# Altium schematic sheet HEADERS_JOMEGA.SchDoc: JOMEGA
size A3; Author: Silvio Navaretti; CompanyName: ARDUINO; DrawnBy: Silvio Navaretti; Engineer: Silvio Navaretti; Organization: ARDUINO; SheetNumber: 22; SheetTotal: 51; RevAuthor: Silvio Navaretti
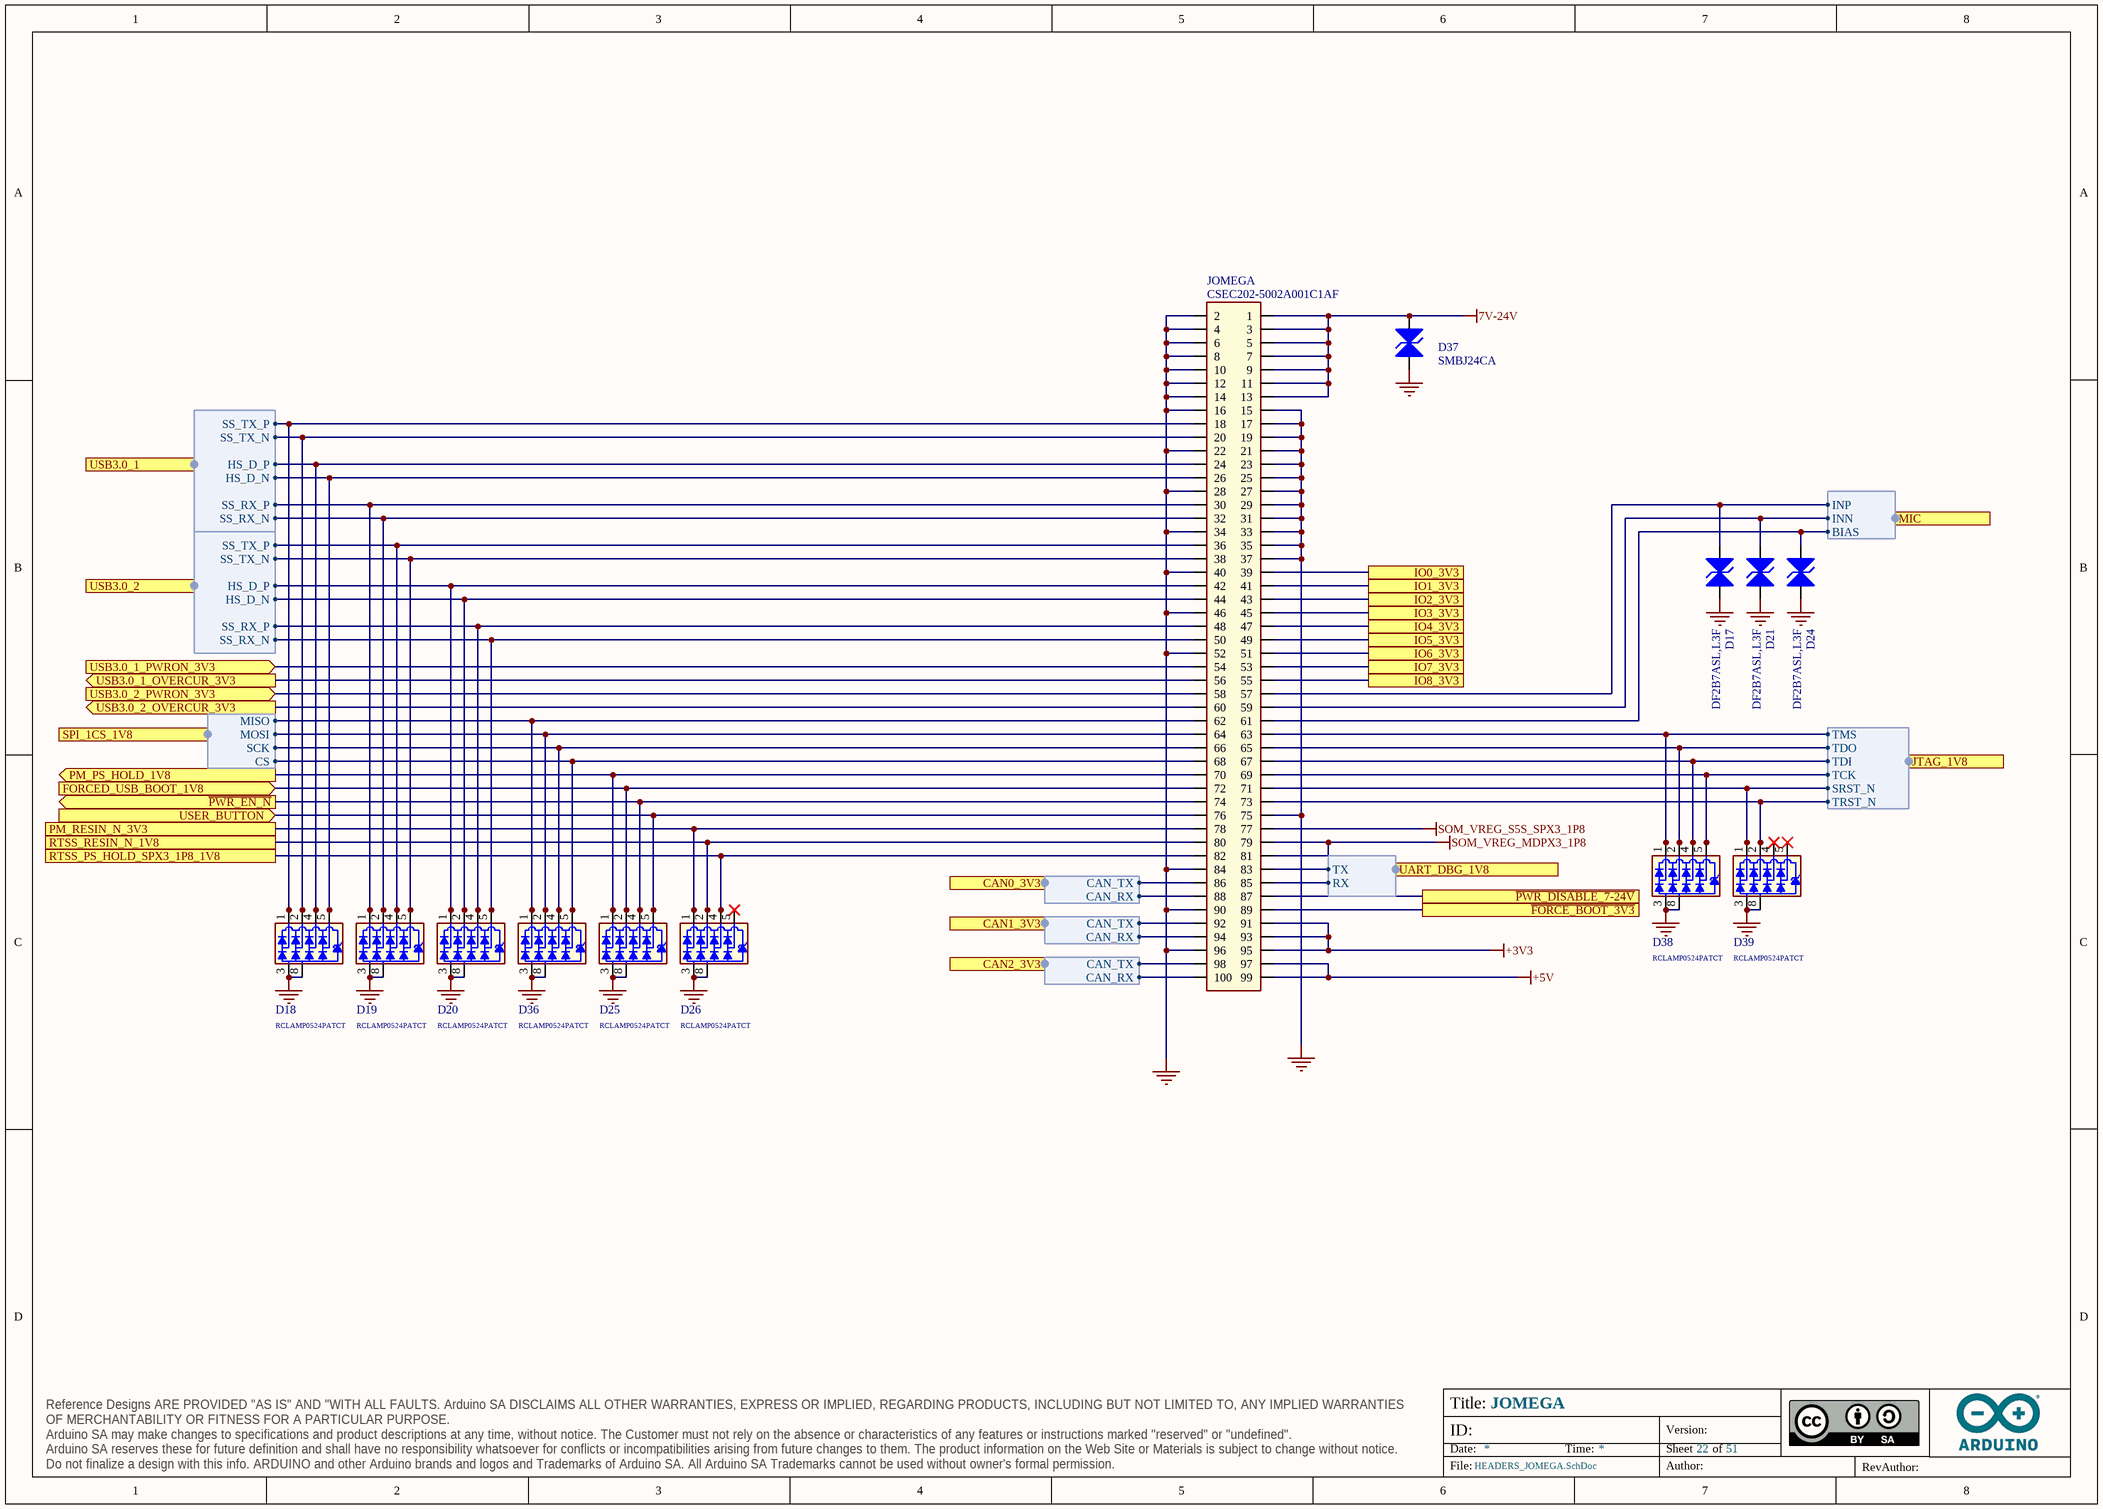
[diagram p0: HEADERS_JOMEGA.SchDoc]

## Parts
D17  DF2B7ASL,L3F  [DF2B7ASL,L3F]
D18  RCLAMP0524PATCT  [SLP2510P8]
D19  RCLAMP0524PATCT  [SLP2510P8]
D20  RCLAMP0524PATCT  [SLP2510P8]
D21  DF2B7ASL,L3F  [DF2B7ASL,L3F]
D24  DF2B7ASL,L3F  [DF2B7ASL,L3F]
D25  RCLAMP0524PATCT  [SLP2510P8]
D26  RCLAMP0524PATCT  [SLP2510P8]
D36  RCLAMP0524PATCT  [SLP2510P8]
D37  SMBJ24CA  [SMB_NOPOLARITY]
D38  RCLAMP0524PATCT  [SLP2510P8]
D39  RCLAMP0524PATCT  [SLP2510P8]
JOMEGA  CSEC202-5002A001C1AF  [CSEC202-5002A001C1AF]

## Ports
CAN0_3V3 (out, harness CAN), CAN1_3V3 (out, harness CAN), CAN2_3V3 (out, harness CAN), FORCED_USB_BOOT_1V8 (in), IO0_3V3, IO1_3V3, IO2_3V3, IO3_3V3, IO4_3V3, IO5_3V3, IO6_3V3, IO7_3V3, IO8_3V3, JTAG_1V8 (out, harness SOM_SAIL_JTAG), MIC (out, harness MIC), PM_PS_HOLD_1V8 (out), PM_RESIN_N_3V3, RTSS_PS_HOLD_SPX3_1P8_1V8, RTSS_RESIN_N_1V8, SPI_1CS_1V8 (in, harness SPI), UART_DBG_1V8 (harness UART), USB3.0_1 (out, harness SOM_MD_USB0), USB3.0_1_OVERCUR_3V3 (out), USB3.0_1_PWRON_3V3 (in), USB3.0_2 (out, harness SOM_MD_USB0), USB3.0_2_OVERCUR_3V3 (out), USB3.0_2_PWRON_3V3 (in), USER_BUTTON (in), ~{FORCE_BOOT_3V3}, ~{PWR_DISABLE_7-24V}, ~{PWR_EN_N} (out)

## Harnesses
MIC: INP, INN, BIAS
SOM_SAIL_JTAG: TMS, TDO, TDI, TCK, SRST_N, TRST_N
SOM_MD_USB0: SS_TX_N, SS_TX_P, HS_D_P, HS_D_N, SS_RX_P, SS_RX_N
SPI: SCK, MISO, MOSI, CS
CAN: CAN_TX, CAN_RX
UART: TX, RX

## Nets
7V-24V: D37.2(A2) JOMEGA.1 JOMEGA.3 JOMEGA.5 JOMEGA.7 JOMEGA.9 JOMEGA.11 JOMEGA.13
+3V3: JOMEGA.91 JOMEGA.93 JOMEGA.95
+5V: JOMEGA.97 JOMEGA.99
GND: D17.1(A1) D18.3 D18.8 D19.3 D19.8 D20.3 D20.8 D21.1(A1) D24.1(A1) D25.3 D25.8 D26.3 D26.8 D36.3 D36.8 D37.1(A1) D38.3 D38.8 D39.3 D39.8 JOMEGA.2 JOMEGA.4 JOMEGA.6 JOMEGA.8 JOMEGA.10 JOMEGA.12 JOMEGA.14 JOMEGA.15 JOMEGA.16 JOMEGA.17 JOMEGA.19 JOMEGA.21 JOMEGA.22 JOMEGA.23 JOMEGA.25 JOMEGA.27 JOMEGA.28 JOMEGA.29 JOMEGA.31 JOMEGA.33 JOMEGA.34 JOMEGA.35 JOMEGA.37 JOMEGA.40 JOMEGA.46 JOMEGA.52 JOMEGA.75 JOMEGA.84 JOMEGA.90 JOMEGA.96
SOM_VREG_MDPX3_1P8: JOMEGA.79 JOMEGA.81
SOM_VREG_S5S_SPX3_1P8: JOMEGA.77
~{FORCE_BOOT_3V3}: JOMEGA.89 ; port ~{FORCE_BOOT_3V3}
FORCED_USB_BOOT_1V8: D25.2 D25.9 JOMEGA.72 ; port FORCED_USB_BOOT_1V8
IO0_3V3: JOMEGA.39 ; port IO0_3V3
IO1_3V3: JOMEGA.41 ; port IO1_3V3
IO2_3V3: JOMEGA.43 ; port IO2_3V3
IO3_3V3: JOMEGA.45 ; port IO3_3V3
IO4_3V3: JOMEGA.47 ; port IO4_3V3
IO5_3V3: JOMEGA.49 ; port IO5_3V3
IO6_3V3: JOMEGA.51 ; port IO6_3V3
IO7_3V3: JOMEGA.53 ; port IO7_3V3
IO8_3V3: JOMEGA.55 ; port IO8_3V3
~{PWR_DISABLE_7-24V}: JOMEGA.87 ; port ~{PWR_DISABLE_7-24V}
~{PWR_EN_N}: D25.4 D25.7 JOMEGA.74 ; port ~{PWR_EN_N}
PM_PS_HOLD_1V8: D25.1 D25.10 JOMEGA.70 ; port PM_PS_HOLD_1V8
PM_RESIN_N_3V3: D26.1 D26.10 JOMEGA.78 ; port PM_RESIN_N_3V3
RTSS_PS_HOLD_SPX3_1P8_1V8: D26.4 D26.7 JOMEGA.82 ; port RTSS_PS_HOLD_SPX3_1P8_1V8
RTSS_RESIN_N_1V8: D26.2 D26.9 JOMEGA.80 ; port RTSS_RESIN_N_1V8
USB3.0_1_OVERCUR_3V3: JOMEGA.56 ; port USB3.0_1_OVERCUR_3V3
USB3.0_1_PWRON_3V3: JOMEGA.54 ; port USB3.0_1_PWRON_3V3
USB3.0_2_OVERCUR_3V3: JOMEGA.60 ; port USB3.0_2_OVERCUR_3V3
USB3.0_2_PWRON_3V3: JOMEGA.58 ; port USB3.0_2_PWRON_3V3
USER_BUTTON: D25.5 D25.6 JOMEGA.76 ; port USER_BUTTON
NetD17_2: D17.2(A2) JOMEGA.57 ; port MIC.INP
NetD18_1: D18.1 D18.10 JOMEGA.18 ; port USB3.0_1.SS_TX_P
NetD18_2: D18.2 D18.9 JOMEGA.20 ; port USB3.0_1.SS_TX_N
NetD18_4: D18.4 D18.7 JOMEGA.24 ; port USB3.0_1.HS_D_P
NetD18_5: D18.5 D18.6 JOMEGA.26 ; port USB3.0_1.HS_D_N
NetD19_1: D19.1 D19.10 JOMEGA.30 ; port USB3.0_1.SS_RX_P
NetD19_2: D19.2 D19.9 JOMEGA.32 ; port USB3.0_1.SS_RX_N
NetD19_4: D19.4 D19.7 JOMEGA.36 ; port USB3.0_2.SS_TX_P
NetD19_5: D19.5 D19.6 JOMEGA.38 ; port USB3.0_2.SS_TX_N
NetD20_1: D20.1 D20.10 JOMEGA.42 ; port USB3.0_2.HS_D_P
NetD20_2: D20.2 D20.9 JOMEGA.44 ; port USB3.0_2.HS_D_N
NetD20_4: D20.4 D20.7 JOMEGA.48 ; port USB3.0_2.SS_RX_P
NetD20_5: D20.5 D20.6 JOMEGA.50 ; port USB3.0_2.SS_RX_N
NetD21_2: D21.2(A2) JOMEGA.59 ; port MIC.INN
NetD24_2: D24.2(A2) JOMEGA.61 ; port MIC.BIAS
NetD26_5: D26.5 D26.6
NetD36_1: D36.1 D36.10 JOMEGA.62 ; port SPI_1CS_1V8.MISO
NetD36_2: D36.2 D36.9 JOMEGA.64 ; port SPI_1CS_1V8.MOSI
NetD36_4: D36.4 D36.7 JOMEGA.66 ; port SPI_1CS_1V8.SCK
NetD36_5: D36.5 D36.6 JOMEGA.68 ; port SPI_1CS_1V8.CS
NetD38_1: D38.1 D38.10 JOMEGA.63 ; port JTAG_1V8.TMS
NetD38_2: D38.2 D38.9 JOMEGA.65 ; port JTAG_1V8.TDO
NetD38_4: D38.4 D38.7 JOMEGA.67 ; port JTAG_1V8.TDI
NetD38_5: D38.5 D38.6 JOMEGA.69 ; port JTAG_1V8.TCK
NetD39_1: D39.1 D39.10 JOMEGA.71 ; port JTAG_1V8.SRST_N
NetD39_2: D39.2 D39.9 JOMEGA.73 ; port JTAG_1V8.TRST_N
NetD39_4: D39.4 D39.7
NetD39_5: D39.5 D39.6
NetJOMEGA_83: JOMEGA.83 ; port UART_DBG_1V8.TX
NetJOMEGA_85: JOMEGA.85 ; port UART_DBG_1V8.RX
NetJOMEGA_86: JOMEGA.86 ; port CAN0_3V3.CAN_TX
NetJOMEGA_88: JOMEGA.88 ; port CAN0_3V3.CAN_RX
NetJOMEGA_92: JOMEGA.92 ; port CAN1_3V3.CAN_TX
NetJOMEGA_94: JOMEGA.94 ; port CAN1_3V3.CAN_RX
NetJOMEGA_98: JOMEGA.98 ; port CAN2_3V3.CAN_TX
NetJOMEGA_100: JOMEGA.100 ; port CAN2_3V3.CAN_RX

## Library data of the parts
D17 D21 D24 = D0099-5: TVS BIDIRECTIONAL SMD Vr 5.5V, Vbr min 5.8V, 0.62x0.32mm; Manufacturer: TOSHIBA; Vforward max: 0V; Ireverse max: 1µA; Power max: 80W; Code Arduino: D0099; Vreverse max: 20V
D18-D20 D25 D26 D36 D38 D39 = D0097-A.6: TVS UNIDIRECTIONAL 4CH 0.8pF 5V SLP2510P8 10-pin 2.5x1.0x0.58mm; Manufacturer: SEMTECH; Code Arduino: D0097; Device Type: ESD protection
D37 = D0070-A.2: TVS BIDIRECTIONAL SMD Vr 24V, Vbr min 26.7V, 600W, SMB; Manufacturer: Littlefuse; V(BR) Typ (V): 26.7; Code Arduino: D0070
JOMEGA = J0574-A.2: CONN HEADER FEMALE VERTICAL SMD 1.27mm 2x50 POS heigth 4.4mm; Manufacturer: Greenconn; Code Arduino: J0574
